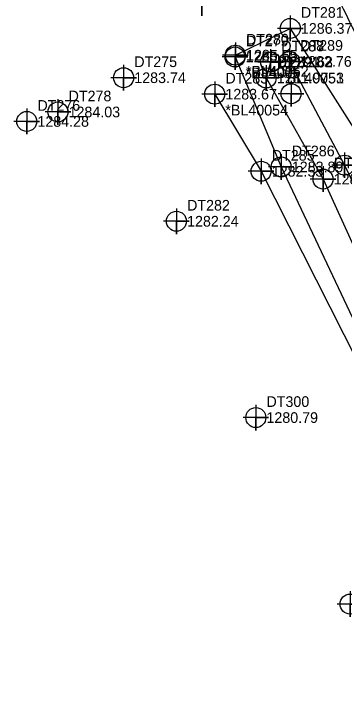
# Model space of a CAD drawing. Extents: x 1394009 to 1394411, y 957864 to 958364.
# Drawn here: x 1394018.3 to 1394095.7, y 958114.8 to 958278.5 of the extents above; entities that cross this region are included whole.
import ezdxf

# ---------------------------------------------------------------- set-up
doc = ezdxf.new("R2010")
doc.units = 0
for name, color, linetype in [('Exist DTM Breakline', 7, 'Continuous'), ('Exist DTM Breakline Cogo Comment', 7, 'Continuous'), ('Exist DTM Breakline Cogo Elevation', 7, 'Continuous'), ('Exist DTM Breakline Cogo Number', 7, 'Continuous'), ('Exist DTM Breakline Cogo Point CELL', 7, 'Continuous'), ('Exist DTM Crownline', 7, 'Continuous'), ('Exist DTM Regular Point Cogo Elevation', 7, 'Continuous'), ('Exist Roads EOP', 7, 'Continuous'), ('PH Exist DTM NCFMP LIDAR Elevation Point', 7, 'Continuous'), ('Raster_Level_0', 7, 'Continuous')]:
    doc.layers.add(name, color=color, linetype=linetype)

msp = doc.modelspace()

# ---------------------------------------------------------------- linework, layer by layer
at = {"layer": 'Exist DTM Breakline'}
for points in [[(1394070.2199, 958268.841), (1394083.0781, 958275.1225), (1394099.617, 958249.0394), (1394120.0982, 958212.652), (1394140.7402, 958174.6816), (1394162.1474, 958145.323), (1394171.088, 958138.1508)], [(1394070.1313, 958268.4251), (1394080.9574, 958242.6289), (1394101.6472, 958198.7507), (1394123.0372, 958162.9752), (1394143.223, 958131.4044), (1394156.1703, 958108.6674), (1394147.5951, 958089.3097), (1394152.395, 958060.7909)], [(1394078.4681, 958267.2162), (1394077.4426, 958263.4985), (1394090.7676, 958239.7722), (1394107.7408, 958202.4417), (1394126.2755, 958165.4231), (1394146.8464, 958135.0295)], [(1394078.4815, 958267.2528), (1394082.9126, 958267.3867), (1394095.8187, 958243.0525), (1394113.4272, 958206.3553), (1394134.4907, 958171.1858), (1394155.1759, 958139.8204), (1394165.1856, 958129.7757), (1394177.2665, 958121.2673), (1394190.9858, 958098.52), (1394181.5225, 958090.4285), (1394174.2125, 958080.1878)], [(1394065.3665, 958259.7005), (1394076.2432, 958241.6096), (1394098.862, 958196.9887), (1394119.1062, 958160.1529), (1394140.102, 958128.983), (1394150.6899, 958110.4316), (1394136.5853, 958093.0812), (1394143.0953, 958059.9522)]]:
    msp.add_lwpolyline(points, dxfattribs=at)
at = {"layer": 'Exist DTM Breakline Cogo Point CELL'}
for points in [[(1394062.3328, 958284.0618), (1394062.3328, 958278.0618), (1394062.3328, 958281.0618), (1394065.3328, 958281.0618), (1394059.3328, 958281.0618)], [(1394083.0781, 958278.1225), (1394083.0781, 958272.1225), (1394083.0781, 958275.1225), (1394086.0781, 958275.1225), (1394080.0781, 958275.1225)], [(1394070.1313, 958271.4251), (1394070.1313, 958265.4251), (1394070.1313, 958268.4251), (1394073.1313, 958268.4251), (1394067.1313, 958268.4251)], [(1394070.2199, 958271.841), (1394070.2199, 958265.841), (1394070.2199, 958268.841), (1394073.2199, 958268.841), (1394067.2199, 958268.841)], [(1394078.4681, 958270.2162), (1394078.4681, 958264.2162), (1394078.4681, 958267.2162), (1394081.4681, 958267.2162), (1394075.4681, 958267.2162)], [(1394078.4815, 958270.2528), (1394078.4815, 958264.2528), (1394078.4815, 958267.2528), (1394081.4815, 958267.2528), (1394075.4815, 958267.2528)], [(1394082.9126, 958270.3867), (1394082.9126, 958264.3867), (1394082.9126, 958267.3867), (1394085.9126, 958267.3867), (1394079.9126, 958267.3867)], [(1394077.4426, 958266.4985), (1394077.4426, 958260.4985), (1394077.4426, 958263.4985), (1394080.4426, 958263.4985), (1394074.4426, 958263.4985)], [(1394065.3665, 958262.7005), (1394065.3665, 958256.7005), (1394065.3665, 958259.7005), (1394068.3665, 958259.7005), (1394062.3665, 958259.7005)], [(1394080.9574, 958245.6289), (1394080.9574, 958239.6289), (1394080.9574, 958242.6289), (1394083.9574, 958242.6289), (1394077.9574, 958242.6289)], [(1394095.8187, 958246.0525), (1394095.8187, 958240.0525), (1394095.8187, 958243.0525), (1394098.8187, 958243.0525), (1394092.8187, 958243.0525)], [(1394076.2432, 958244.6096), (1394076.2432, 958238.6096), (1394076.2432, 958241.6096), (1394079.2432, 958241.6096), (1394073.2432, 958241.6096)], [(1394090.7676, 958242.7722), (1394090.7676, 958236.7722), (1394090.7676, 958239.7722), (1394093.7676, 958239.7722), (1394087.7676, 958239.7722)]]:
    msp.add_lwpolyline(points, dxfattribs=at)
for centre in [(1394083.0781, 958275.1225), (1394070.2199, 958268.841), (1394070.1313, 958268.4251), (1394078.4681, 958267.2162), (1394078.4815, 958267.2528), (1394082.9126, 958267.3867), (1394077.4426, 958263.4985), (1394065.3665, 958259.7005), (1394080.9574, 958242.6289), (1394095.8187, 958243.0525), (1394076.2432, 958241.6096), (1394090.7676, 958239.7722)]:
    msp.add_circle(centre, 2.344, dxfattribs=at)
at = {"layer": 'Exist DTM Crownline'}
msp.add_spline([(1394087.9321, 958316.4176), (1394109.0623, 958273.1922), (1394131.7594, 958230.1822), (1394152.5248, 958192.8438), (1394173.9492, 958155.4634)], degree=3, dxfattribs=at)
at = {"layer": 'Exist Roads EOP'}
msp.add_spline([(1394078.897, 958312.8974), (1394101.0229, 958268.6968), (1394123.3315, 958225.72), (1394144.2526, 958188.5895), (1394165.818, 958150.9033)], degree=3, dxfattribs=at)
at = {"layer": 'PH Exist DTM NCFMP LIDAR Elevation Point'}
for points in [[(1394044.0101, 958266.558), (1394044.0101, 958260.558), (1394044.0101, 958263.558), (1394047.0101, 958263.558), (1394041.0101, 958263.558)], [(1394083.2854, 958262.8129), (1394083.2854, 958256.8129), (1394083.2854, 958259.8129), (1394086.2854, 958259.8129), (1394080.2854, 958259.8129)], [(1394028.6056, 958258.5231), (1394028.6056, 958252.5231), (1394028.6056, 958255.5231), (1394031.6056, 958255.5231), (1394025.6056, 958255.5231)], [(1394021.2998, 958256.304), (1394021.2998, 958250.304), (1394021.2998, 958253.304), (1394024.2998, 958253.304), (1394018.2998, 958253.304)], [(1394056.3907, 958232.8892), (1394056.3907, 958226.8892), (1394056.3907, 958229.8892), (1394059.3907, 958229.8892), (1394053.3907, 958229.8892)], [(1394075.0032, 958186.8302), (1394075.0032, 958180.8302), (1394075.0032, 958183.8302), (1394078.0032, 958183.8302), (1394072.0032, 958183.8302)], [(1394097.1059, 958143.0857), (1394097.1059, 958137.0857), (1394097.1059, 958140.0857), (1394100.1059, 958140.0857), (1394094.1059, 958140.0857)]]:
    msp.add_lwpolyline(points, dxfattribs=at)
for centre in [(1394044.0101, 958263.558), (1394083.2854, 958259.8129), (1394028.6056, 958255.5231), (1394021.2998, 958253.304), (1394056.3907, 958229.8892), (1394075.0032, 958183.8302), (1394097.1059, 958140.0857)]:
    msp.add_circle(centre, 2.344, dxfattribs=at)

# ---------------------------------------------------------------- texts
at = {"layer": 'Exist DTM Breakline Cogo Comment'}
for s, p in [('*BL40052', (1394072.7199, 958263.841)), ('*BL4005', (1394072.6313, 958263.4251)), ('*BL40051', (1394080.9681, 958262.2162)), ('*BL40053', (1394080.9815, 958262.2528)), ('*BL40054', (1394067.8665, 958254.7005))]:
    msp.add_text(s, height=2.5, dxfattribs=at).set_placement(p)
at = {"layer": 'Exist DTM Breakline Cogo Elevation'}
for s, p in [('1286.37', (1394085.5781, 958273.8725)), ('1285.53', (1394072.6313, 958267.1751)), ('1285.55', (1394072.7199, 958267.591)), ('1282.62', (1394080.9681, 958265.9662)), ('1282.63', (1394080.9815, 958266.0028)), ('1282.76', (1394085.4126, 958266.1367)), ('1281.97', (1394079.9426, 958262.2485)), ('1283.67', (1394067.8665, 958258.4505)), ('1283.89', (1394083.4574, 958241.3789)), ('1282.53', (1394078.7432, 958240.3596)), ('1280.84', (1394093.2676, 958238.5222))]:
    msp.add_text(s, height=2.5, dxfattribs=at).set_placement(p)
at = {"layer": 'Exist DTM Breakline Cogo Number'}
for s, p in [('DT281', (1394085.5781, 958277.6225)), ('DT279', (1394072.6313, 958270.9251)), ('DT280', (1394072.7199, 958271.341)), ('DT287', (1394080.9681, 958269.7162)), ('DT288', (1394080.9815, 958269.7528)), ('DT289', (1394085.4126, 958269.8867)), ('DT291', (1394079.9426, 958265.9985)), ('DT283', (1394067.8665, 958262.2005)), ('DT285', (1394078.7432, 958244.1096)), ('DT286', (1394083.4574, 958245.1289)), ('DT292', (1394093.2676, 958242.2722))]:
    msp.add_text(s, height=2.5, dxfattribs=at).set_placement(p)
at = {"layer": 'Exist DTM Regular Point Cogo Elevation'}
for s, p in [('1283.74', (1394046.5101, 958262.308)), ('1284.03', (1394031.1056, 958254.2731)), ('1284.28', (1394023.7998, 958252.054)), ('1282.24', (1394058.8907, 958228.6392)), ('1280.79', (1394077.5032, 958182.5802))]:
    msp.add_text(s, height=2.5, dxfattribs=at).set_placement(p)
at = {"layer": 'Raster_Level_0'}
for s, p in [('DT275', (1394046.5101, 958266.058)), ('DT278', (1394031.1056, 958258.0231)), ('DT276', (1394023.7998, 958255.804)), ('DT282', (1394058.8907, 958232.3892)), ('DT300', (1394077.5032, 958186.3302))]:
    msp.add_text(s, height=2.5, dxfattribs=at).set_placement(p)

doc.saveas('drawing.dxf')
